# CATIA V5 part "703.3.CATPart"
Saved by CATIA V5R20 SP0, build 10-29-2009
Part number: 703.3
Revision: ANY
Definition: UNKNOWN
Nomenclature: 703.3
Source: Unknown
Bounding box of the stored display mesh (mm): x -40 to 40, y -40 to 40, z 0 to 25
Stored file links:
  C:\Users\Utente\Desktop\IO LAVORO\3D X SITO CF\X 3D SITO CF 27-09-2020\703\703.3.CATPart
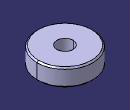
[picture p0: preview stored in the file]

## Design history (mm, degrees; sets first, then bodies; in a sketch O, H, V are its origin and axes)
Body1 "Foro lamato per Vite M12 a testa cilindrica-1" (main body)
  Solid1: solid without history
